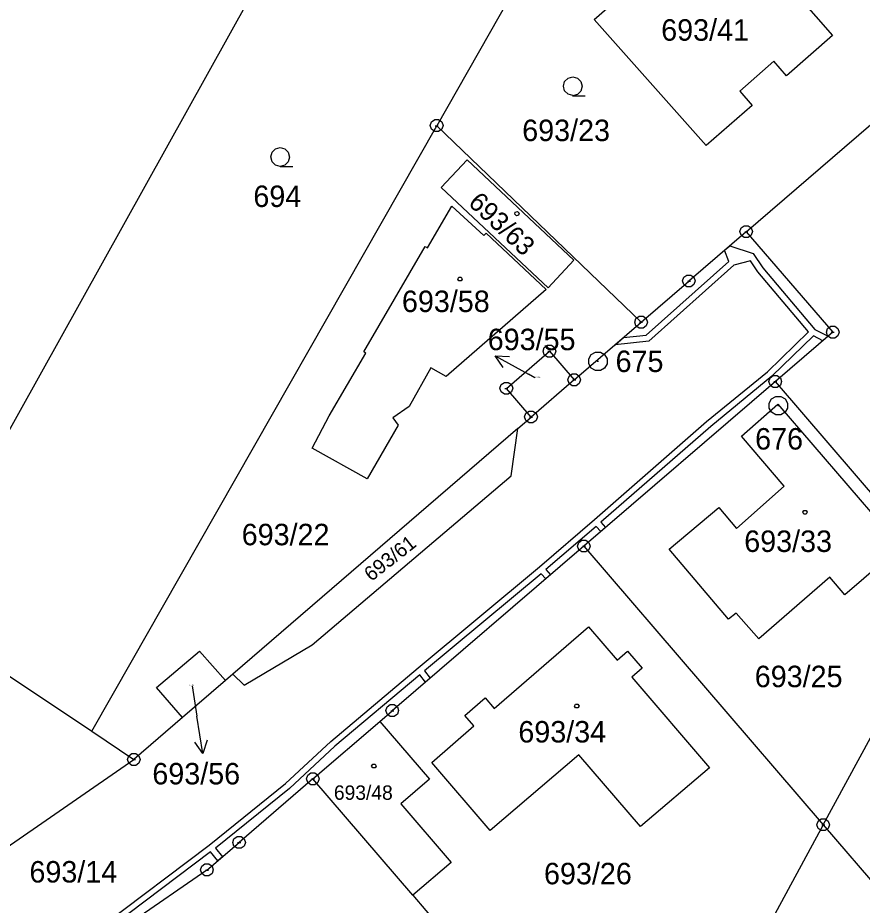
# Model space of a CAD drawing. Extents: x -759699 to -757730, y -1172308 to -1170857.
# Drawn here: x -758338.2 to -758271.3, y -1171206.6 to -1171136.3 of the extents above; entities that cross this region are included whole.
import ezdxf

# ---------------------------------------------------------------- set-up
doc = ezdxf.new("R2010")
doc.units = 0
for name, color, linetype in [('Vrstva 1', 7, 'Continuous'), ('Vrstva 12', 7, 'Continuous'), ('Vrstva 13', 7, 'Continuous'), ('Vrstva 2', 7, 'Continuous'), ('Vrstva 3', 7, 'Continuous'), ('Vrstva 5', 7, 'Continuous'), ('Vrstva 7', 7, 'Continuous'), ('Vrstva 8', 7, 'Continuous')]:
    doc.layers.add(name, color=color, linetype=linetype)

msp = doc.modelspace()

# ---------------------------------------------------------------- linework, layer by layer
at = {"layer": 'Vrstva 1'}
for p, q in [((-758346.54, -1171182.75), (-758307.35, -1171112.41)), ((-758290.15, -1171118.76), (-758304.99, -1171144.84)), ((-758292.53, -1171136.42), (-758282.43, -1171127.64)), ((-758282.43, -1171127.64), (-758273.63, -1171137.69)), ((-758280.48, -1171153.24), (-758259.47, -1171135.14)), ((-758283.65, -1171146.42), (-758292.53, -1171136.42)), ((-758273.63, -1171137.69), (-758277.28, -1171140.9)), ((-758278.28, -1171139.73), (-758280.98, -1171142.11)), ((-758277.28, -1171140.9), (-758278.28, -1171139.73)), ((-758280.98, -1171142.11), (-758280, -1171143.25)), ((-758280, -1171143.25), (-758283.65, -1171146.42)), ((-758326.7, -1171182.96), (-758304.99, -1171144.84)), ((-758288.8, -1171160.41), (-758304.99, -1171144.84)), ((-758304.63, -1171149.73), (-758302.58, -1171147.55)), ((-758302.58, -1171147.55), (-758294.12, -1171155.49)), ((-758296.17, -1171157.67), (-758304.63, -1171149.73)), ((-758305.73, -1171154.51), (-758303.8, -1171151.21)), ((-758303.8, -1171151.21), (-758301.25, -1171153.55)), ((-758301.25, -1171153.55), (-758301.07, -1171153.35)), ((-758301.07, -1171153.35), (-758296.31, -1171157.82)), ((-758280.48, -1171153.24), (-758285.02, -1171157.15)), ((-758280.48, -1171153.24), (-758273.62, -1171161.2)), ((-758310.77, -1171162.75), (-758305.9, -1171154.41)), ((-758305.9, -1171154.41), (-758305.73, -1171154.51)), ((-758294.12, -1171155.49), (-758296.17, -1171157.67)), ((-758288.8, -1171160.41), (-758285.02, -1171157.15)), ((-758296.31, -1171157.82), (-758304.24, -1171164.71)), ((-758294.1, -1171164.98), (-758288.8, -1171160.41)), ((-758273.62, -1171161.2), (-758278.17, -1171165.11)), ((-758299.47, -1171165.65), (-758296.06, -1171162.71)), ((-758296.06, -1171162.71), (-758294.1, -1171164.98)), ((-758313.51, -1171167.82), (-758310.6, -1171162.85)), ((-758310.6, -1171162.85), (-758310.77, -1171162.75)), ((-758305.47, -1171164.03), (-758307.18, -1171167.08)), ((-758304.24, -1171164.71), (-758305.47, -1171164.03)), ((-758294.1, -1171164.98), (-758297.52, -1171167.92)), ((-758278.17, -1171165.11), (-758293.33, -1171178.14)), ((-758264.18, -1171181.4), (-758278.17, -1171165.11)), ((-758297.52, -1171167.92), (-758299.47, -1171165.65)), ((-758280.84, -1171169.42), (-758277.97, -1171166.9)), ((-758277.97, -1171166.9), (-758268.27, -1171178.18)), ((-758307.18, -1171167.08), (-758308.46, -1171167.97)), ((-758314.87, -1171170.38), (-758313.51, -1171167.82)), ((-758308.46, -1171167.97), (-758308.05, -1171168.56)), ((-758298.56, -1171168.82), (-758297.52, -1171167.92)), ((-758298.56, -1171168.82), (-758321.14, -1171188.28)), ((-758308.05, -1171168.56), (-758310.5, -1171172.8)), ((-758299.1, -1171172.56), (-758298.56, -1171168.82)), ((-758277.47, -1171173.38), (-758280.84, -1171169.42)), ((-758310.5, -1171172.8), (-758314.87, -1171170.38)), ((-758314.85, -1171185.95), (-758299.1, -1171172.56)), ((-758281.24, -1171176.75), (-758277.47, -1171173.38)), ((-758286.58, -1171178.38), (-758282.65, -1171175.07)), ((-758282.65, -1171175.07), (-758281.24, -1171176.75)), ((-758293.33, -1171178.14), (-758308.51, -1171191.17)), ((-758293.33, -1171178.14), (-758274.38, -1171200.21)), ((-758268.27, -1171178.18), (-758272.66, -1171182)), ((-758281.89, -1171183.91), (-758286.58, -1171178.38)), ((-758273.85, -1171180.59), (-758279.49, -1171185.48)), ((-758272.66, -1171182), (-758273.85, -1171180.59)), ((-758274.38, -1171200.21), (-758264.18, -1171181.4)), ((-758329.08, -1171187.15), (-758326.7, -1171182.96)), ((-758281.27, -1171183.45), (-758281.89, -1171183.91)), ((-758279.49, -1171185.48), (-758281.27, -1171183.45)), ((-758345.18, -1171184.23), (-758332.3, -1171192.8)), ((-758300.44, -1171191), (-758292.96, -1171184.53)), ((-758292.96, -1171184.53), (-758290.71, -1171187.16)), ((-758327.19, -1171189.33), (-758323.77, -1171186.47)), ((-758323.77, -1171186.47), (-758321.73, -1171188.79)), ((-758320.24, -1171189.15), (-758314.85, -1171185.95)), ((-758290.71, -1171187.16), (-758289.88, -1171186.46)), ((-758289.88, -1171186.46), (-758288.73, -1171187.81)), ((-758332.3, -1171192.8), (-758329.08, -1171187.15)), ((-758288.73, -1171187.81), (-758289.54, -1171188.52)), ((-758321.14, -1171188.28), (-758321.73, -1171188.79)), ((-758321.14, -1171188.28), (-758320.24, -1171189.15)), ((-758289.54, -1171188.52), (-758283.39, -1171195.7)), ((-758325.12, -1171191.71), (-758327.19, -1171189.33)), ((-758321.73, -1171188.79), (-758325.12, -1171191.71)), ((-758302.76, -1171191.54), (-758301.16, -1171190.16)), ((-758301.16, -1171190.16), (-758300.44, -1171191)), ((-758309.5, -1171192.02), (-758308.51, -1171191.17)), ((-758325.12, -1171191.71), (-758328.98, -1171195.04)), ((-758314.8, -1171196.58), (-758309.5, -1171192.02)), ((-758309.5, -1171192.02), (-758305.56, -1171196.6)), ((-758302.04, -1171192.38), (-758302.76, -1171191.54)), ((-758332.3, -1171192.8), (-758328.98, -1171195.04)), ((-758305.38, -1171195.27), (-758302.04, -1171192.38)), ((-758365.62, -1171220.33), (-758328.98, -1171195.04)), ((-758293.73, -1171194.66), (-758300.75, -1171200.67)), ((-758288.86, -1171200.35), (-758293.73, -1171194.66)), ((-758300.75, -1171200.67), (-758305.38, -1171195.27)), ((-758283.39, -1171195.7), (-758288.86, -1171200.35)), ((-758314.8, -1171196.58), (-758320.64, -1171201.61)), ((-758306.89, -1171205.79), (-758314.8, -1171196.58)), ((-758305.56, -1171196.6), (-758307.83, -1171198.56)), ((-758307.83, -1171198.56), (-758303.85, -1171203.19)), ((-758274.38, -1171200.21), (-758284.58, -1171219.02)), ((-758274.38, -1171200.21), (-758267.94, -1171207.71)), ((-758323.19, -1171203.79), (-758320.64, -1171201.61)), ((-758303.85, -1171203.19), (-758306.89, -1171205.79)), ((-758323.19, -1171203.79), (-758329.24, -1171207.97)), ((-758306.89, -1171205.79), (-758288.83, -1171226.85))]:
    msp.add_line(p, q, dxfattribs=at)
at = {"layer": 'Vrstva 12'}
for p, q in [((-758292.53, -1171136.42), (-758282.43, -1171127.64)), ((-758282.43, -1171127.64), (-758273.63, -1171137.69)), ((-758283.65, -1171146.42), (-758292.53, -1171136.42)), ((-758273.63, -1171137.69), (-758277.28, -1171140.9)), ((-758278.28, -1171139.73), (-758280.98, -1171142.11)), ((-758277.28, -1171140.9), (-758278.28, -1171139.73)), ((-758280.98, -1171142.11), (-758280, -1171143.25)), ((-758280, -1171143.25), (-758283.65, -1171146.42)), ((-758304.63, -1171149.73), (-758302.58, -1171147.55)), ((-758302.58, -1171147.55), (-758294.12, -1171155.49)), ((-758296.17, -1171157.67), (-758304.63, -1171149.73)), ((-758305.73, -1171154.51), (-758303.8, -1171151.21)), ((-758303.8, -1171151.21), (-758301.25, -1171153.55)), ((-758301.25, -1171153.55), (-758301.07, -1171153.35)), ((-758301.07, -1171153.35), (-758296.31, -1171157.82)), ((-758310.77, -1171162.75), (-758305.9, -1171154.41)), ((-758305.9, -1171154.41), (-758305.73, -1171154.51)), ((-758294.12, -1171155.49), (-758296.17, -1171157.67)), ((-758296.31, -1171157.82), (-758304.24, -1171164.71)), ((-758313.51, -1171167.82), (-758310.6, -1171162.85)), ((-758310.6, -1171162.85), (-758310.77, -1171162.75)), ((-758305.47, -1171164.03), (-758307.18, -1171167.08)), ((-758304.24, -1171164.71), (-758305.47, -1171164.03)), ((-758280.84, -1171169.42), (-758277.97, -1171166.9)), ((-758277.97, -1171166.9), (-758268.27, -1171178.18)), ((-758307.18, -1171167.08), (-758308.46, -1171167.97)), ((-758314.87, -1171170.38), (-758313.51, -1171167.82)), ((-758308.46, -1171167.97), (-758308.05, -1171168.56)), ((-758308.05, -1171168.56), (-758310.5, -1171172.8)), ((-758277.47, -1171173.38), (-758280.84, -1171169.42)), ((-758310.5, -1171172.8), (-758314.87, -1171170.38)), ((-758281.24, -1171176.75), (-758277.47, -1171173.38)), ((-758286.58, -1171178.38), (-758282.65, -1171175.07)), ((-758282.65, -1171175.07), (-758281.24, -1171176.75)), ((-758268.27, -1171178.18), (-758272.66, -1171182)), ((-758281.89, -1171183.91), (-758286.58, -1171178.38)), ((-758273.85, -1171180.59), (-758279.49, -1171185.48)), ((-758272.66, -1171182), (-758273.85, -1171180.59)), ((-758281.27, -1171183.45), (-758281.89, -1171183.91)), ((-758279.49, -1171185.48), (-758281.27, -1171183.45)), ((-758300.44, -1171191), (-758292.96, -1171184.53)), ((-758292.96, -1171184.53), (-758290.71, -1171187.16)), ((-758290.71, -1171187.16), (-758289.88, -1171186.46)), ((-758289.88, -1171186.46), (-758288.73, -1171187.81)), ((-758288.73, -1171187.81), (-758289.54, -1171188.52)), ((-758289.54, -1171188.52), (-758283.39, -1171195.7)), ((-758302.76, -1171191.54), (-758301.16, -1171190.16)), ((-758301.16, -1171190.16), (-758300.44, -1171191)), ((-758314.8, -1171196.58), (-758309.5, -1171192.02)), ((-758309.5, -1171192.02), (-758305.56, -1171196.6)), ((-758302.04, -1171192.38), (-758302.76, -1171191.54)), ((-758305.38, -1171195.27), (-758302.04, -1171192.38)), ((-758293.73, -1171194.66), (-758300.75, -1171200.67)), ((-758288.86, -1171200.35), (-758293.73, -1171194.66)), ((-758300.75, -1171200.67), (-758305.38, -1171195.27)), ((-758283.39, -1171195.7), (-758288.86, -1171200.35)), ((-758306.89, -1171205.79), (-758314.8, -1171196.58)), ((-758305.56, -1171196.6), (-758307.83, -1171198.56)), ((-758307.83, -1171198.56), (-758303.85, -1171203.19)), ((-758303.85, -1171203.19), (-758306.89, -1171205.79))]:
    msp.add_line(p, q, dxfattribs=at)
at = {"layer": 'Vrstva 13'}
for p, q in [((-758282.19, -1171154.71), (-758281.78, -1171154.36)), ((-758281.86, -1171155.59), (-758282.19, -1171154.71)), ((-758281.78, -1171154.36), (-758279.92, -1171154.97)), ((-758279.92, -1171154.97), (-758279.17, -1171156.11)), ((-758288.41, -1171161.43), (-758281.86, -1171155.59)), ((-758280.14, -1171155.55), (-758281.45, -1171155.89)), ((-758279.57, -1171156.41), (-758280.14, -1171155.55)), ((-758281.45, -1171155.89), (-758288.19, -1171161.91)), ((-758279.17, -1171156.11), (-758275.04, -1171160.99)), ((-758275.54, -1171161.17), (-758279.57, -1171156.41)), ((-758278.8, -1171164.33), (-758275.54, -1171161.17)), ((-758275.04, -1171160.99), (-758273.99, -1171161.52)), ((-758290.87, -1171162.2), (-758290.21, -1171161.62)), ((-758288.19, -1171161.91), (-758290.87, -1171162.2)), ((-758290.21, -1171161.62), (-758288.41, -1171161.43)), ((-758275.15, -1171161.49), (-758278.46, -1171164.69)), ((-758274.4, -1171161.87), (-758275.15, -1171161.49)), ((-758273.99, -1171161.52), (-758274.4, -1171161.87)), ((-758283.61, -1171168.28), (-758278.8, -1171164.33)), ((-758278.46, -1171164.69), (-758283.29, -1171168.66)), ((-758292.5, -1171176.04), (-758283.61, -1171168.28)), ((-758283.29, -1171168.66), (-758291.99, -1171176.25)), ((-758296.86, -1171179.78), (-758292.5, -1171176.04)), ((-758292.36, -1171176.58), (-758296.34, -1171179.99)), ((-758292, -1171176.99), (-758292.36, -1171176.58)), ((-758291.62, -1171176.67), (-758292, -1171176.99)), ((-758291.99, -1171176.25), (-758291.62, -1171176.67)), ((-758306.46, -1171187.78), (-758296.86, -1171179.78)), ((-758296.34, -1171179.99), (-758295.97, -1171180.4)), ((-758296.73, -1171180.32), (-758305.96, -1171188.01)), ((-758296.36, -1171180.74), (-758296.73, -1171180.32)), ((-758295.97, -1171180.4), (-758296.36, -1171180.74)), ((-758313.39, -1171193.61), (-758306.46, -1171187.78)), ((-758305.96, -1171188.01), (-758305.51, -1171188.6)), ((-758306.34, -1171188.33), (-758313.05, -1171193.99)), ((-758305.89, -1171188.92), (-758306.34, -1171188.33)), ((-758305.51, -1171188.6), (-758305.89, -1171188.92)), ((-758316.97, -1171196.95), (-758313.39, -1171193.61)), ((-758313.05, -1171193.99), (-758316.65, -1171197.33)), ((-758323.01, -1171201.81), (-758316.97, -1171196.95)), ((-758316.65, -1171197.33), (-758322.51, -1171202.05)), ((-758332.85, -1171209.22), (-758323.01, -1171201.81)), ((-758322.51, -1171202.05), (-758321.96, -1171202.74)), ((-758322.9, -1171202.36), (-758332.3, -1171209.43)), ((-758322.34, -1171203.06), (-758322.9, -1171202.36)), ((-758321.96, -1171202.74), (-758322.34, -1171203.06))]:
    msp.add_line(p, q, dxfattribs=at)
at = {"layer": 'Vrstva 3'}
for points in [[(-758294.21, -1171142.45), (-758294.59, -1171142.35), (-758294.86, -1171142.08), (-758294.96, -1171141.71), (-758294.86, -1171141.34), (-758294.59, -1171141.07), (-758294.22, -1171140.97), (-758293.85, -1171141.07), (-758293.58, -1171141.34), (-758293.48, -1171141.72), (-758293.58, -1171142.1), (-758293.85, -1171142.37), (-758294.23, -1171142.47), (-758293.23, -1171142.47)], [(-758317.38, -1171148.06), (-758317.76, -1171147.96), (-758318.03, -1171147.69), (-758318.13, -1171147.32), (-758318.03, -1171146.95), (-758317.76, -1171146.68), (-758317.39, -1171146.58), (-758317.02, -1171146.68), (-758316.75, -1171146.95), (-758316.65, -1171147.33), (-758316.75, -1171147.71), (-758317.02, -1171147.98), (-758317.4, -1171148.08), (-758316.4, -1171148.08)]]:
    msp.add_lwpolyline(points, dxfattribs=at)
at = {"layer": 'Vrstva 5'}
for points in [[(-758298.472, -1171151.762), (-758298.509, -1171151.933), (-758298.677, -1171151.981), (-758298.808, -1171151.858), (-758298.771, -1171151.687), (-758298.603, -1171151.639)], [(-758303.06, -1171156.84), (-758302.97, -1171156.99), (-758303.06, -1171157.14), (-758303.24, -1171157.14), (-758303.33, -1171156.99), (-758303.24, -1171156.84)], [(-758275.73, -1171175.31), (-758275.64, -1171175.46), (-758275.73, -1171175.61), (-758275.91, -1171175.61), (-758276, -1171175.46), (-758275.91, -1171175.31)], [(-758293.81, -1171190.65), (-758293.72, -1171190.8), (-758293.81, -1171190.95), (-758293.99, -1171190.95), (-758294.08, -1171190.8), (-758293.99, -1171190.65)], [(-758309.88, -1171195.41), (-758309.79, -1171195.56), (-758309.88, -1171195.71), (-758310.06, -1171195.71), (-758310.15, -1171195.56), (-758310.06, -1171195.41)]]:
    msp.add_lwpolyline(points, close=True, dxfattribs=at)
at = {"layer": 'Vrstva 7'}
for p, q in [((-758300.349, -1171163.066), (-758297.73, -1171164.53)), ((-758297.23, -1171164.81), (-758297.73, -1171164.53)), ((-758324.37, -1171189.2), (-758323.98, -1171191.6)), ((-758323.51, -1171194.563), (-758323.98, -1171191.6))]:
    msp.add_line(p, q, dxfattribs=at)
for points in [[(-758299.72, -1171163.99), (-758300.349, -1171163.066), (-758299.232, -1171163.118)], [(-758323.173, -1171193.497), (-758323.51, -1171194.563), (-758324.16, -1171193.654)]]:
    msp.add_lwpolyline(points, dxfattribs=at)
at = {"layer": 'Vrstva 8'}
for p, q in [((-758305.11, -1171144.84), (-758304.87, -1171144.84)), ((-758280.6, -1171153.24), (-758280.36, -1171153.24)), ((-758285.14, -1171157.15), (-758284.9, -1171157.15)), ((-758288.92, -1171160.41), (-758288.68, -1171160.41)), ((-758273.74, -1171161.2), (-758273.5, -1171161.2)), ((-758296.18, -1171162.71), (-758295.94, -1171162.71)), ((-758292.27, -1171163.5), (-758292.17, -1171163.5)), ((-758294.22, -1171164.98), (-758293.98, -1171164.98)), ((-758278.29, -1171165.11), (-758278.05, -1171165.11)), ((-758299.59, -1171165.65), (-758299.35, -1171165.65)), ((-758277.98, -1171167), (-758277.88, -1171167)), ((-758297.64, -1171167.92), (-758297.4, -1171167.92)), ((-758293.45, -1171178.14), (-758293.21, -1171178.14)), ((-758308.63, -1171191.17), (-758308.39, -1171191.17)), ((-758329.1, -1171195.04), (-758328.86, -1171195.04)), ((-758314.92, -1171196.58), (-758314.68, -1171196.58)), ((-758274.5, -1171200.21), (-758274.26, -1171200.21)), ((-758320.76, -1171201.61), (-758320.52, -1171201.61)), ((-758323.31, -1171203.79), (-758323.07, -1171203.79))]:
    msp.add_line(p, q, dxfattribs=at)
for points in [[(-758304.84, -1171144.36), (-758304.59, -1171144.54), (-758304.49, -1171144.83), (-758304.59, -1171145.12), (-758304.84, -1171145.3), (-758305.15, -1171145.3), (-758305.4, -1171145.12), (-758305.5, -1171144.83), (-758305.4, -1171144.54), (-758305.15, -1171144.36)], [(-758280.33, -1171152.76), (-758280.08, -1171152.94), (-758279.98, -1171153.23), (-758280.08, -1171153.52), (-758280.33, -1171153.7), (-758280.64, -1171153.7), (-758280.89, -1171153.52), (-758280.99, -1171153.23), (-758280.89, -1171152.94), (-758280.64, -1171152.76)], [(-758284.87, -1171156.67), (-758284.62, -1171156.85), (-758284.52, -1171157.14), (-758284.62, -1171157.43), (-758284.87, -1171157.61), (-758285.18, -1171157.61), (-758285.43, -1171157.43), (-758285.53, -1171157.14), (-758285.43, -1171156.85), (-758285.18, -1171156.67)], [(-758288.65, -1171159.93), (-758288.4, -1171160.11), (-758288.3, -1171160.4), (-758288.4, -1171160.69), (-758288.65, -1171160.87), (-758288.96, -1171160.87), (-758289.21, -1171160.69), (-758289.31, -1171160.4), (-758289.21, -1171160.11), (-758288.96, -1171159.93)], [(-758273.47, -1171160.72), (-758273.22, -1171160.9), (-758273.12, -1171161.19), (-758273.22, -1171161.48), (-758273.47, -1171161.66), (-758273.78, -1171161.66), (-758274.03, -1171161.48), (-758274.13, -1171161.19), (-758274.03, -1171160.9), (-758273.78, -1171160.72)], [(-758295.91, -1171162.23), (-758295.66, -1171162.41), (-758295.56, -1171162.7), (-758295.66, -1171162.99), (-758295.91, -1171163.17), (-758296.22, -1171163.17), (-758296.47, -1171162.99), (-758296.57, -1171162.7), (-758296.47, -1171162.41), (-758296.22, -1171162.23)], [(-758292.03, -1171162.78), (-758291.69, -1171162.97), (-758291.5, -1171163.31), (-758291.5, -1171163.7), (-758291.69, -1171164.04), (-758292.03, -1171164.23), (-758292.42, -1171164.23), (-758292.76, -1171164.04), (-758292.95, -1171163.7), (-758292.95, -1171163.31), (-758292.76, -1171162.97), (-758292.42, -1171162.78)], [(-758293.95, -1171164.5), (-758293.7, -1171164.68), (-758293.6, -1171164.97), (-758293.7, -1171165.26), (-758293.95, -1171165.44), (-758294.26, -1171165.44), (-758294.51, -1171165.26), (-758294.61, -1171164.97), (-758294.51, -1171164.68), (-758294.26, -1171164.5)], [(-758278.02, -1171164.63), (-758277.77, -1171164.81), (-758277.67, -1171165.1), (-758277.77, -1171165.39), (-758278.02, -1171165.57), (-758278.33, -1171165.57), (-758278.58, -1171165.39), (-758278.68, -1171165.1), (-758278.58, -1171164.81), (-758278.33, -1171164.63)], [(-758299.32, -1171165.17), (-758299.07, -1171165.35), (-758298.97, -1171165.64), (-758299.07, -1171165.93), (-758299.32, -1171166.11), (-758299.63, -1171166.11), (-758299.88, -1171165.93), (-758299.98, -1171165.64), (-758299.88, -1171165.35), (-758299.63, -1171165.17)], [(-758277.74, -1171166.28), (-758277.4, -1171166.47), (-758277.21, -1171166.81), (-758277.21, -1171167.2), (-758277.4, -1171167.54), (-758277.74, -1171167.73), (-758278.13, -1171167.73), (-758278.47, -1171167.54), (-758278.66, -1171167.2), (-758278.66, -1171166.81), (-758278.47, -1171166.47), (-758278.13, -1171166.28)], [(-758297.37, -1171167.44), (-758297.12, -1171167.62), (-758297.02, -1171167.91), (-758297.12, -1171168.2), (-758297.37, -1171168.38), (-758297.68, -1171168.38), (-758297.93, -1171168.2), (-758298.03, -1171167.91), (-758297.93, -1171167.62), (-758297.68, -1171167.44)], [(-758293.18, -1171177.66), (-758292.93, -1171177.84), (-758292.83, -1171178.13), (-758292.93, -1171178.42), (-758293.18, -1171178.6), (-758293.49, -1171178.6), (-758293.74, -1171178.42), (-758293.84, -1171178.13), (-758293.74, -1171177.84), (-758293.49, -1171177.66)], [(-758308.36, -1171190.69), (-758308.11, -1171190.87), (-758308.01, -1171191.16), (-758308.11, -1171191.45), (-758308.36, -1171191.63), (-758308.67, -1171191.63), (-758308.92, -1171191.45), (-758309.02, -1171191.16), (-758308.92, -1171190.87), (-758308.67, -1171190.69)], [(-758328.83, -1171194.56), (-758328.58, -1171194.74), (-758328.48, -1171195.03), (-758328.58, -1171195.32), (-758328.83, -1171195.5), (-758329.14, -1171195.5), (-758329.39, -1171195.32), (-758329.49, -1171195.03), (-758329.39, -1171194.74), (-758329.14, -1171194.56)], [(-758314.65, -1171196.1), (-758314.4, -1171196.28), (-758314.3, -1171196.57), (-758314.4, -1171196.86), (-758314.65, -1171197.04), (-758314.96, -1171197.04), (-758315.21, -1171196.86), (-758315.31, -1171196.57), (-758315.21, -1171196.28), (-758314.96, -1171196.1)], [(-758274.23, -1171199.73), (-758273.98, -1171199.91), (-758273.88, -1171200.2), (-758273.98, -1171200.49), (-758274.23, -1171200.67), (-758274.54, -1171200.67), (-758274.79, -1171200.49), (-758274.89, -1171200.2), (-758274.79, -1171199.91), (-758274.54, -1171199.73)], [(-758320.49, -1171201.13), (-758320.24, -1171201.31), (-758320.14, -1171201.6), (-758320.24, -1171201.89), (-758320.49, -1171202.07), (-758320.8, -1171202.07), (-758321.05, -1171201.89), (-758321.15, -1171201.6), (-758321.05, -1171201.31), (-758320.8, -1171201.13)], [(-758323.04, -1171203.31), (-758322.79, -1171203.49), (-758322.69, -1171203.78), (-758322.79, -1171204.07), (-758323.04, -1171204.25), (-758323.35, -1171204.25), (-758323.6, -1171204.07), (-758323.7, -1171203.78), (-758323.6, -1171203.49), (-758323.35, -1171203.31)]]:
    msp.add_lwpolyline(points, close=True, dxfattribs=at)

# ---------------------------------------------------------------- texts
at = {"layer": 'Vrstva 2'}
for s, height, p in [('693/41', 1.7, (-758287.211, -1171138.11)), ('693/23', 1.7, (-758298.22, -1171146.06)), ('694', 1.7, (-758319.514, -1171151.28)), ('693/58', 1.7, (-758307.746, -1171159.6)), ('693/55', 0.1, (-758297.209, -1171164.81)), ('693/22', 1.7, (-758320.437, -1171178.07)), ('693/33', 1.7, (-758280.634, -1171178.6)), ('693/25', 1.7, (-758279.8, -1171189.31)), ('693/56', 0.1, (-758324.62, -1171189.2)), ('693/34', 1.7, (-758298.526, -1171193.69)), ('693/48', 1.14, (-758313.136, -1171198.23)), ('693/14', 1.7, (-758337.251, -1171204.78)), ('693/26', 1.7, (-758296.493, -1171204.92))]:
    msp.add_text(s, height=height, dxfattribs=at).set_placement(p)
for s, height, rotation, p in [('693/63', 1.5, 316.78836, (-758302.575, -1171151.05)), ('693/61', 1.14, 38.21629, (-758310.174, -1171180.982))]:
    msp.add_text(s, height=height, rotation=rotation, dxfattribs=at).set_placement(p)
at = {"layer": 'Vrstva 7'}
for s, p in [('693/55', (-758300.953, -1171162.62)), ('693/56', (-758327.516, -1171197.01))]:
    msp.add_text(s, height=1.7, dxfattribs=at).set_placement(p)
at = {"layer": 'Vrstva 8'}
for s, p in [('675', (-758290.824, -1171164.35)), ('676', (-758279.77, -1171170.49))]:
    msp.add_text(s, height=1.7, dxfattribs=at).set_placement(p)

doc.saveas('drawing.dxf')
